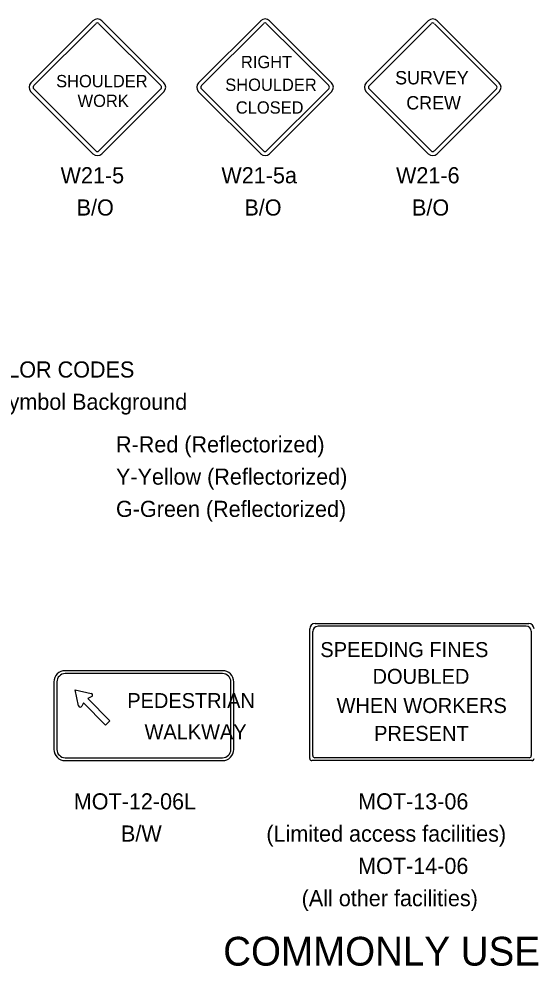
# Model space of a CAD drawing. Extents: x 10000 to 10794, y 10000 to 10499.
# Drawn here: x 10396.1 to 10507.5, y 10043.8 to 10249.3 of the extents above; entities that cross this region are included whole.
import ezdxf

# ---------------------------------------------------------------- set-up
doc = ezdxf.new("R2010")
doc.units = 0
for name, color, linetype in [('DSIndex', 7, 'Continuous'), ('DSText', 7, 'Continuous'), ('DSTitle', 7, 'Continuous'), ('PlotBorder_dp', 7, 'Continuous')]:
    doc.layers.add(name, color=color, linetype=linetype)

msp = doc.modelspace()

# ---------------------------------------------------------------- linework, layer by layer
at = {"layer": 'DSIndex'}
for p, q in [((10435.1, 10235.42), (10448.58, 10248.89)), ((10435.73, 10234.81), (10449.18, 10248.26)), ((10449.88, 10248.26), (10463.34, 10234.81)), ((10450.49, 10248.89), (10463.97, 10235.42)), ((10448.58, 10220.02), (10435.1, 10233.5)), ((10449.18, 10220.65), (10435.73, 10234.11)), ((10463.34, 10234.11), (10449.88, 10220.65)), ((10463.97, 10233.5), (10450.49, 10220.02)), ((10459.24, 10108.62), (10459.24, 10116.99)), ((10459.89, 10108.65), (10459.89, 10116.39)), ((10460.37, 10118.12), (10506.78, 10118.12)), ((10506.18, 10117.53), (10461.02, 10117.53)), ((10507.29, 10116.43), (10507.29, 10089.47)), ((10459.24, 10088.8), (10459.24, 10108.71)), ((10459.89, 10089.47), (10459.89, 10108.71)), ((10408.3, 10103.71), (10411.81, 10102.94)), ((10409.07, 10100.27), (10408.3, 10103.71)), ((10411.94, 10102.28), (10411.07, 10101.84)), ((10411.07, 10101.84), (10415.88, 10097.03)), ((10410.14, 10100.91), (10409.79, 10100.19)), ((10414.95, 10096.09), (10410.14, 10100.91)), ((10415.88, 10097.03), (10414.95, 10096.09)), ((10507.45, 10088.37), (10459.67, 10088.37)), ((10506.86, 10089.01), (10460.35, 10089.01))]:
    msp.add_line(p, q, dxfattribs=at)
for points in [[(10440.32, 10107.88), (10406.18, 10107.88)], [(10440.32, 10107.25), (10406.18, 10107.25)], [(10403.74, 10105.44), (10403.74, 10090.81)], [(10404.37, 10105.44), (10404.37, 10090.81)], [(10442.13, 10090.81), (10442.13, 10105.44)], [(10442.76, 10090.81), (10442.76, 10105.44)], [(10406.18, 10089), (10440.32, 10089)], [(10406.18, 10088.37), (10440.32, 10088.37)]]:
    msp.add_lwpolyline(points, dxfattribs=at)
for centre, radius, start, end in [((10449.53, 10247.93), 1.36, 45, 135), ((10449.53, 10247.92), 0.49, 45, 135), ((10436.06, 10234.46), 1.36, 135, 225), ((10463, 10234.46), 1.36, 315, 45), ((10436.07, 10234.46), 0.49, 135, 225), ((10462.99, 10234.46), 0.49, 315, 45), ((10449.53, 10220.99), 1.36, 225, 315), ((10449.53, 10221), 0.49, 225, 315), ((10460.37, 10116.99), 1.13, 90, 180), ((10461.02, 10116.39), 1.13, 90, 180), ((10506.16, 10116.39), 1.13, 2.0407, 90), ((10506.76, 10116.99), 1.13, 0, 90), ((10406.18, 10105.44), 2.44, 90, 180), ((10406.18, 10105.44), 1.81, 90, 180), ((10440.32, 10105.44), 2.44, 0, 90), ((10440.32, 10105.44), 1.81, 0, 90), ((10406.18, 10090.81), 2.44, 180, 270), ((10406.18, 10090.81), 1.81, 180, 270), ((10440.32, 10090.81), 2.44, 270, 360), ((10440.32, 10090.81), 1.81, 270, 360), ((10459.7, 10088.83), 0.464, 183.7813, 266.3447), ((10460.35, 10089.47), 0.464, 180, 270), ((10506.83, 10089.47), 0.464, 270, 0), ((10507.43, 10088.83), 0.464, 270, 360)]:
    msp.add_arc(centre, radius, start, end, dxfattribs=at)
for centre, major_axis, start_param, end_param in [((10411.78, 10102.59), (0.254, -0.254), 5.92785, 8.579191), ((10409.44, 10100.35), (0.274, -0.274), 4.142184, 6.609592)]:
    msp.add_ellipse(centre, major_axis=major_axis, ratio=0.967097, start_param=start_param, end_param=end_param, dxfattribs=at)
at = {"layer": 'DSText'}
for p, q in [((10398.72, 10235.42), (10412.19, 10248.89)), ((10414.11, 10248.89), (10427.58, 10235.42)), ((10471.48, 10235.41), (10484.95, 10248.89)), ((10486.87, 10248.89), (10500.34, 10235.41)), ((10412.19, 10220.02), (10398.72, 10233.5)), ((10427.58, 10233.5), (10414.11, 10220.02)), ((10484.95, 10220.02), (10471.48, 10233.5)), ((10500.34, 10233.5), (10486.87, 10220.02))]:
    msp.add_line(p, q, dxfattribs=at)
for centre, start, end in [((10413.15, 10247.93), 45, 135), ((10485.91, 10247.93), 45, 135), ((10399.68, 10234.46), 135, 225), ((10426.62, 10234.46), 315, 45), ((10472.44, 10234.46), 135, 225), ((10499.38, 10234.46), 315, 45), ((10413.15, 10220.99), 225, 315), ((10485.91, 10220.99), 225, 315)]:
    msp.add_arc(centre, 1.36, start, end, dxfattribs=at)
at = {"layer": 'DSTitle'}
for p, q in [((10399.34, 10234.81), (10412.8, 10248.26)), ((10413.5, 10248.26), (10426.95, 10234.81)), ((10472.1, 10234.8), (10485.56, 10248.26)), ((10486.26, 10248.26), (10499.71, 10234.8)), ((10412.8, 10220.65), (10399.34, 10234.11)), ((10426.95, 10234.11), (10413.5, 10220.65)), ((10485.56, 10220.65), (10472.1, 10234.11)), ((10499.71, 10234.11), (10486.26, 10220.65))]:
    msp.add_line(p, q, dxfattribs=at)
for centre, start, end in [((10413.15, 10247.92), 45, 135), ((10485.91, 10247.92), 45, 135), ((10399.69, 10234.46), 135, 225), ((10426.61, 10234.46), 315, 45), ((10472.45, 10234.46), 135, 225), ((10499.37, 10234.46), 315, 45), ((10413.15, 10221), 225, 315), ((10485.91, 10221), 225, 315)]:
    msp.add_arc(centre, 0.49, start, end, dxfattribs=at)

# ---------------------------------------------------------------- texts
at = {"layer": 'DSIndex'}
for s, height, p in [('RIGHT', 2.67, (10444.3, 10238.61)), ('SHOULDER', 2.67, (10440.9, 10233.67)), ('CLOSED', 2.67, (10443.19, 10228.74)), ('W21-5a', 3.5, (10440.06, 10213.62)), ('B/O', 3.5, (10445.05, 10206.63)), ('SPEEDING FINES', 3.2498, (10461.52, 10110.83)), ('DOUBLED', 3.25, (10472.85, 10105.03)), ('PEDESTRIAN ', 3.2386, (10419.65, 10099.78)), ('WHEN WORKERS', 3.2498, (10465.05, 10098.7)), ('WALKWAY', 3.239, (10423.39, 10093)), ('PRESENT', 3.25, (10473.19, 10092.66)), ('MOT-12-06L', 3.5, (10408.03, 10077.78)), ('MOT-13-06', 3.5, (10469.72, 10077.78)), ('B/W', 3.5, (10418.27, 10070.8)), ('(Limited access facilities)', 3.5, (10449.81, 10070.78)), ('MOT-14-06', 3.5, (10469.72, 10063.78)), ('(All other facilities)', 3.5, (10457.47, 10056.78))]:
    msp.add_text(s, height=height, dxfattribs=at).set_placement(p)
at = {"layer": 'PlotBorder_dp'}
for s, height, p in [('SURVEY', 2.901, (10477.75, 10235.08)), ('SHOULDER', 2.67, (10404.21, 10234.46)), ('WORK', 2.67, (10408.86, 10230.19)), ('CREW', 2.901, (10480.17, 10229.64)), ('W21-5', 3.5, (10405.17, 10213.62)), ('W21-6', 3.5, (10477.95, 10213.62)), ('B/O', 3.5, (10408.66, 10206.63)), ('B/O', 3.5, (10481.42, 10206.63)), ('COLOR CODES', 3.5, (10386.58, 10171.48)), ('Legend and/or Symbol Background', 3.5, (10359.27, 10164.48)), ('R-Red (Reflectorized)', 3.5, (10417.19, 10155.24)), ('Y-Yellow (Reflectorized)', 3.5, (10417.19, 10148.24)), ('G-Green (Reflectorized)', 3.5, (10417.19, 10141.24)), ('COMMONLY USED WARNING AND REGULATORY SIGNS IN WORK ZONES', 6.25, (10440.45, 10043.89))]:
    msp.add_text(s, height=height, dxfattribs=at).set_placement(p)

doc.saveas('drawing.dxf')
